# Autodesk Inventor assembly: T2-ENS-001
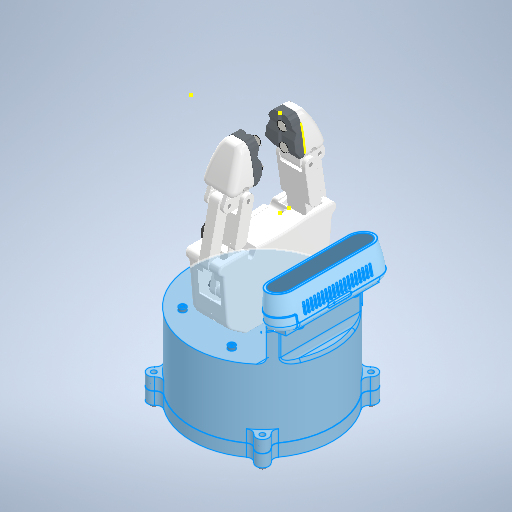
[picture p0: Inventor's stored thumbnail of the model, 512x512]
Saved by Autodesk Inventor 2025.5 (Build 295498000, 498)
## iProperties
Created: 2026-10
Part Number: T2-ENS-001
Document SubType Name: Assembly
Designer: Luis MuÃ±oz
Project: TESIS 2 - Plataforma mecatrÃ³nica preventiva desacoplada
Description: Sistema de gripper instrumentado para JACO2
Author: Luis M
Title: Sistema de gripper instrumentado para JACO2
Revision Number: 00
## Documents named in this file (6)
- C:\Users\Luis M\Desktop\TESIS\CAD_TESIS_PRUEBA_MIGRACION\04_SISTEMA_COMPLETO\IAM\SISTEMA_GRIPPER_INSTRUMENTADO_JACO2.iam
- C:\Users\Luis M\Desktop\TESIS\CAD_TESIS_PRUEBA_MIGRACION\02_ELECTRONICA\IAM\MODULO_ELECTRONICA_PERCEPCION_RGBD.iam
- C:\Users\Luis M\Desktop\TESIS\CAD_TESIS_PRUEBA_MIGRACION\01_GRIPPER\IAM\GRIPPER_ADAPTATIVO_INSTRUMENTADO.iam
- C:\Users\Luis M\Desktop\TESIS\CAD_TESIS_PRUEBA_MIGRACION\05_BIBLIOTECA_COMERCIAL\FIJACIONES\TORNILLO_HEX_INTERIOR_M3X8.ipt
- C:\Users\Luis M\Desktop\TESIS\CAD_TESIS_PRUEBA_MIGRACION\05_BIBLIOTECA_COMERCIAL\FIJACIONES\TORNILLO_HEX_INTERIOR_M3X16.ipt
- C:\Users\Luis M\Desktop\TESIS\CAD_TESIS_PRUEBA_MIGRACION\05_BIBLIOTECA_COMERCIAL\SENSORES\FSR_DF9-40.iam
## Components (15 placed, 5 different names)
1. MODULO_ELECTRONICA_PERCEPCION_RGBD:1 [sub-assembly]
2. GRIPPER_ADAPTATIVO_INSTRUMENTADO:1 [sub-assembly] — Coincidencia:1, Coincidencia:2, Coincidencia:3, Coincidencia:18, Coincidencia:19, Coincidencia:20, Coincidencia:21
3. TORNILLO_HEX_INTERIOR_M3X8:1 — Nivelación:2, Coincidencia:9
4. TORNILLO_HEX_INTERIOR_M3X8:2 — Nivelación:3, Coincidencia:5
5. TORNILLO_HEX_INTERIOR_M3X8:3 — Nivelación:1, Nivelación:2, Coincidencia:4, Coincidencia:6
6. TORNILLO_HEX_INTERIOR_M3X8:4 — Nivelación:1, Nivelación:3, Nivelación:4, Coincidencia:7
7. TORNILLO_HEX_INTERIOR_M3X8:5 — Nivelación:4, Coincidencia:8
8. hex_socket_cylindrical_head_M3x16:1 — Nivelación:6, Coincidencia:22
9. hex_socket_cylindrical_head_M3x16:2 — Nivelación:7, Coincidencia:24, Coincidencia:26
10. hex_socket_cylindrical_head_M3x16:3 — Nivelación:5, Nivelación:6, Nivelación:7, Coincidencia:23
11. hex_socket_cylindrical_head_M3x16:4 — Nivelación:5, Coincidencia:25
12. FSR_DF9-40:1 [sub-assembly] — Coincidencia:19
13. FSR_DF9-40:2 [sub-assembly] — Coincidencia:18
14. FSR_DF9-40:3 [sub-assembly] — Coincidencia:21
15. FSR_DF9-40:4 [sub-assembly] — Coincidencia:20
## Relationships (25: Mate 18, Flush 7)
- Coincidencia:1 [Mate]: GRIPPER_ADAPTATIVO_INSTRUMENTADO:1
- Coincidencia:2 [Mate]: GRIPPER_ADAPTATIVO_INSTRUMENTADO:1
- Coincidencia:3 [Mate]: GRIPPER_ADAPTATIVO_INSTRUMENTADO:1
- Nivelación:1 [Flush]: TORNILLO_HEX_INTERIOR_M3X8:3 ↔ TORNILLO_HEX_INTERIOR_M3X8:4
- Nivelación:2 [Flush]: TORNILLO_HEX_INTERIOR_M3X8:1 ↔ TORNILLO_HEX_INTERIOR_M3X8:3
- Nivelación:3 [Flush]: TORNILLO_HEX_INTERIOR_M3X8:2 ↔ TORNILLO_HEX_INTERIOR_M3X8:4
- Nivelación:4 [Flush]: TORNILLO_HEX_INTERIOR_M3X8:4 ↔ TORNILLO_HEX_INTERIOR_M3X8:5
- Coincidencia:4 [Mate]: TORNILLO_HEX_INTERIOR_M3X8:3
- Coincidencia:5 [Mate]: TORNILLO_HEX_INTERIOR_M3X8:2
- Coincidencia:6 [Mate]: TORNILLO_HEX_INTERIOR_M3X8:3
- Coincidencia:7 [Mate]: TORNILLO_HEX_INTERIOR_M3X8:4
- Coincidencia:8 [Mate]: TORNILLO_HEX_INTERIOR_M3X8:5
- Coincidencia:9 [Mate]: TORNILLO_HEX_INTERIOR_M3X8:1
- Nivelación:5 [Flush]: hex_socket_cylindrical_head_M3x16:3 ↔ hex_socket_cylindrical_head_M3x16:4
- Nivelación:6 [Flush]: hex_socket_cylindrical_head_M3x16:1 ↔ hex_socket_cylindrical_head_M3x16:3
- Nivelación:7 [Flush]: hex_socket_cylindrical_head_M3x16:2 ↔ hex_socket_cylindrical_head_M3x16:3
- Coincidencia:18 [Mate]: GRIPPER_ADAPTATIVO_INSTRUMENTADO:1 ↔ FSR_DF9-40:2
- Coincidencia:19 [Mate]: GRIPPER_ADAPTATIVO_INSTRUMENTADO:1 ↔ FSR_DF9-40:1
- Coincidencia:20 [Mate]: GRIPPER_ADAPTATIVO_INSTRUMENTADO:1 ↔ FSR_DF9-40:4
- Coincidencia:21 [Mate]: GRIPPER_ADAPTATIVO_INSTRUMENTADO:1 ↔ FSR_DF9-40:3
- Coincidencia:22 [Mate]: hex_socket_cylindrical_head_M3x16:1
- Coincidencia:23 [Mate]: hex_socket_cylindrical_head_M3x16:3
- Coincidencia:24 [Mate]: hex_socket_cylindrical_head_M3x16:2
- Coincidencia:25 [Mate]: hex_socket_cylindrical_head_M3x16:4
- Coincidencia:26 [Mate]: hex_socket_cylindrical_head_M3x16:2
